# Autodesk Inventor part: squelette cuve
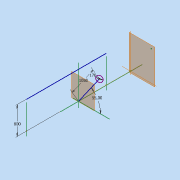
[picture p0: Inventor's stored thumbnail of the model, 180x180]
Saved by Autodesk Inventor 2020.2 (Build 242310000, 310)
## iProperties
Created: 2020-04
Part Number: squelette cuve
Material: Générique
Document SubType Name: Modeling
Designer: t.sancier
Density: 1 g/cm^3
Appearance: Par défaut
Author: t.sancier
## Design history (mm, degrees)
node "Plan altitude 1000"
node "Plan altitude 2500"
sketch "Esquisse virole"
  geometry: L1 (800, 3000)-(800, 700); L2 (-120, 700)-(720, 700) reference; L3 (-120, 3000)-(720, 3000) reference; L4 (0, -340)-(0, 2040) reference; 1 further point
  constraints: 2 end point, 2 point on line, 1 vertical
  dimensions: "d2" = 800 distance between parallel lines of L4 L1
node "Plan altitude 1300"
sketch "Esquisse piquage 1"
  geometry: L1 (0, -160)-(0, 960) reference; L2 (-149.007, 0)-(894.04, 0) reference; L3 (0, 0)-(602.255, 860.11)
  constraints: 2 end point
  dimensions: "d4" = 1050 distance of L3.start L3.end; "d6" = 55 deg angle of L3 L2
node "Plan face bride1"
sketch "Esquisse ouverture1"
  geometry: C1 r 85 at (0, 0); 1 further point
  constraints: 1 centre point
  dimensions: "d7" = 170 diameter of C1
